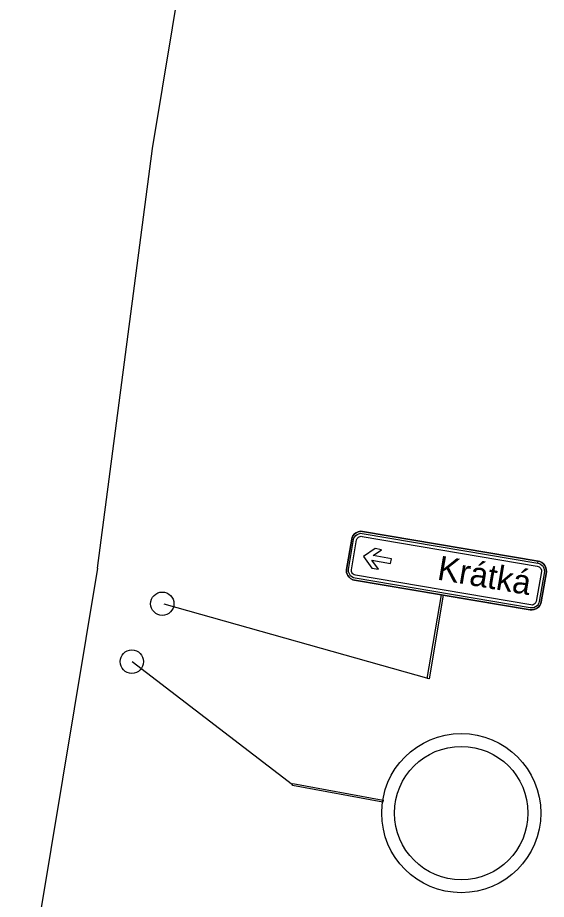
# Model space of a CAD drawing. Extents: x -559605 to -559051, y -1075984 to -1075185.
# Drawn here: x -559202.64 to -559184.53, y -1075394.39 to -1075364.2 of the extents above; entities that cross this region are included whole.
import ezdxf

# ---------------------------------------------------------------- set-up
doc = ezdxf.new("R2010")
doc.units = 0
for name, color, linetype in [('_zarezani_asfaltu', 7, 'Continuous'), ('Svisle DZ stavajici', 7, 'Continuous'), ('Znacky_navrh', 7, 'Continuous')]:
    doc.layers.add(name, color=color, linetype=linetype)

msp = doc.modelspace()

# ---------------------------------------------------------------- linework, layer by layer
at = {"layer": '_zarezani_asfaltu'}
msp.add_line((-559199.909, -1075383.048), (-559202.645, -1075399.578), dxfattribs=at)
msp.add_lwpolyline([(-559199.909, -1075383.048), (-559198.019, -1075368.683), (-559195.291, -1075352.211), (-559191.08, -1075334.685), (-559190.194, -1075332.188)], dxfattribs=at)
at = {"layer": 'Svisle DZ stavajici'}
msp.add_line((-559184.823, -1075382.88), (-559184.81, -1075382.814), dxfattribs=at)
for points in [[(-559190.831, -1075381.793), (-559184.81, -1075382.814), (-559184.751, -1075382.827), (-559184.689, -1075382.859), (-559184.626, -1075382.908), (-559184.585, -1075382.959), (-559184.546, -1075383.034), (-559184.533, -1075383.101), (-559184.529, -1075383.172), (-559184.705, -1075384.206), (-559184.72, -1075384.262), (-559184.75, -1075384.325), (-559184.798, -1075384.387), (-559184.864, -1075384.437), (-559184.944, -1075384.47), (-559185.018, -1075384.482), (-559185.089, -1075384.48), (-559191.098, -1075383.461), (-559191.164, -1075383.446), (-559191.237, -1075383.403), (-559191.285, -1075383.361), (-559191.326, -1075383.303), (-559191.352, -1075383.251), (-559191.372, -1075383.195), (-559191.378, -1075383.138), (-559191.376, -1075383.094), (-559191.199, -1075382.053), (-559191.183, -1075382), (-559191.156, -1075381.947), (-559191.099, -1075381.88), (-559191.046, -1075381.838), (-559190.979, -1075381.809), (-559190.934, -1075381.797), (-559190.887, -1075381.789)], [(-559190.84, -1075381.86), (-559184.823, -1075382.88), (-559184.774, -1075382.891), (-559184.725, -1075382.916), (-559184.673, -1075382.956), (-559184.641, -1075382.995), (-559184.61, -1075383.056), (-559184.599, -1075383.109), (-559184.596, -1075383.169), (-559184.77, -1075384.192), (-559184.783, -1075384.239), (-559184.807, -1075384.29), (-559184.846, -1075384.339), (-559184.897, -1075384.378), (-559184.963, -1075384.405), (-559185.023, -1075384.415), (-559185.083, -1075384.413), (-559191.085, -1075383.395), (-559191.139, -1075383.383), (-559191.198, -1075383.349), (-559191.235, -1075383.316), (-559191.268, -1075383.269), (-559191.29, -1075383.225), (-559191.306, -1075383.18), (-559191.311, -1075383.136), (-559191.309, -1075383.101), (-559191.133, -1075382.068), (-559191.12, -1075382.025), (-559191.1, -1075381.984), (-559191.052, -1075381.928), (-559191.012, -1075381.896), (-559190.956, -1075381.872), (-559190.92, -1075381.862), (-559190.884, -1075381.856)], [(-559190.842, -1075381.962), (-559184.84, -1075382.98), (-559184.777, -1075383.004), (-559184.717, -1075383.063), (-559184.699, -1075383.118), (-559184.698, -1075383.16), (-559184.875, -1075384.197), (-559184.898, -1075384.241), (-559184.916, -1075384.265), (-559184.944, -1075384.286), (-559184.985, -1075384.307), (-559185.019, -1075384.313), (-559185.066, -1075384.312), (-559191.068, -1075383.294), (-559191.109, -1075383.282), (-559191.145, -1075383.259), (-559191.174, -1075383.232), (-559191.193, -1075383.199), (-559191.205, -1075383.163), (-559191.209, -1075383.135), (-559191.208, -1075383.112), (-559191.033, -1075382.083), (-559191.014, -1075382.039), (-559190.993, -1075382.011), (-559190.965, -1075381.987), (-559190.94, -1075381.974), (-559190.907, -1075381.963), (-559190.875, -1075381.96)], [(-559188.063, -1075383.976), (-559188.55, -1075386.846), (-559188.614, -1075386.835), (-559188.127, -1075383.965)]]:
    msp.add_lwpolyline(points, close=True, dxfattribs=at)
for points in [[(-559184.81, -1075382.814), (-559190.831, -1075381.793), (-559190.887, -1075381.789), (-559190.934, -1075381.797), (-559190.979, -1075381.809), (-559191.046, -1075381.838), (-559191.099, -1075381.88), (-559191.156, -1075381.947), (-559191.183, -1075382), (-559191.199, -1075382.053), (-559191.376, -1075383.094), (-559191.378, -1075383.138), (-559191.372, -1075383.195), (-559191.352, -1075383.251), (-559191.326, -1075383.303), (-559191.285, -1075383.361), (-559191.237, -1075383.403), (-559191.164, -1075383.446), (-559191.098, -1075383.461), (-559188.127, -1075383.965), (-559188.063, -1075383.976), (-559185.089, -1075384.48), (-559185.018, -1075384.482), (-559184.944, -1075384.47), (-559184.864, -1075384.437), (-559184.798, -1075384.387), (-559184.75, -1075384.325), (-559184.72, -1075384.262), (-559184.705, -1075384.206), (-559184.529, -1075383.172), (-559184.533, -1075383.101), (-559184.546, -1075383.034), (-559184.585, -1075382.959), (-559184.626, -1075382.908), (-559184.689, -1075382.859), (-559184.751, -1075382.827), (-559184.81, -1075382.814)], [(-559184.823, -1075382.88), (-559184.774, -1075382.891), (-559184.725, -1075382.916), (-559184.673, -1075382.956), (-559184.641, -1075382.995), (-559184.61, -1075383.056), (-559184.599, -1075383.109), (-559184.596, -1075383.169), (-559184.77, -1075384.192), (-559184.783, -1075384.239), (-559184.807, -1075384.29), (-559184.846, -1075384.339), (-559184.897, -1075384.378), (-559184.963, -1075384.405), (-559185.023, -1075384.415), (-559185.083, -1075384.413), (-559191.085, -1075383.395), (-559191.139, -1075383.383), (-559191.198, -1075383.349), (-559191.235, -1075383.316), (-559191.268, -1075383.269), (-559191.29, -1075383.225), (-559191.306, -1075383.18), (-559191.311, -1075383.136), (-559191.309, -1075383.101), (-559191.133, -1075382.068), (-559191.12, -1075382.025), (-559191.1, -1075381.984), (-559191.052, -1075381.928), (-559191.012, -1075381.896), (-559190.956, -1075381.872), (-559190.92, -1075381.862), (-559190.884, -1075381.856), (-559190.84, -1075381.86), (-559184.823, -1075382.88)], [(-559189.839, -1075382.728), (-559190.461, -1075382.623), (-559190.173, -1075382.419), (-559190.398, -1075382.38), (-559190.789, -1075382.656), (-559190.511, -1075383.046), (-559190.286, -1075383.085), (-559190.504, -1075382.778), (-559189.865, -1075382.886), (-559189.839, -1075382.728)], [(-559188.55, -1075386.846), (-559197.624, -1075384.287)]]:
    msp.add_lwpolyline(points, dxfattribs=at)
msp.add_circle((-559197.689, -1075384.269), 0.4, dxfattribs=at)
at = {"layer": 'Znacky_navrh'}
msp.add_line((-559198.72, -1075386.243), (-559193.225, -1075390.459), dxfattribs=at)
msp.add_lwpolyline([(-559190.133, -1075391.061), (-559193.231, -1075390.493), (-559193.218, -1075390.425), (-559190.12, -1075390.992)], close=True, dxfattribs=at)
for centre, radius in [((-559198.731, -1075386.253), 0.4), ((-559187.445, -1075391.439), 2.725), ((-559187.445, -1075391.439), 2.285)]:
    msp.add_circle(centre, radius, dxfattribs=at)

# ---------------------------------------------------------------- texts
at = {"layer": 'Svisle DZ stavajici'}
msp.add_text('Krátká', height=0.8318, rotation=350.374, dxfattribs=at).set_placement((-559188.298, -1075383.437))

doc.saveas('drawing.dxf')
